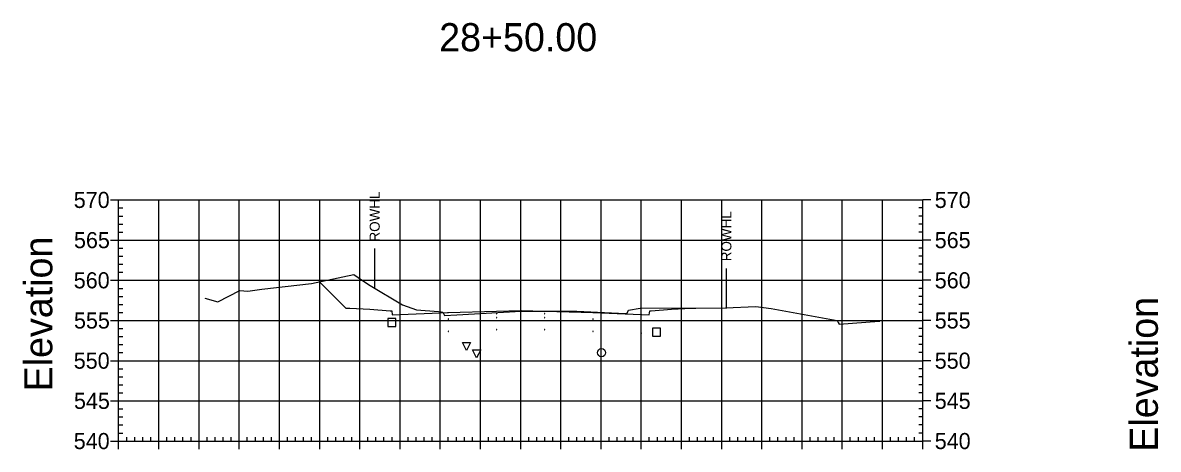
# Model space of a CAD drawing. Extents: x 708103 to 717568, y 374476 to 378707.
# Drawn here: x 710028.1 to 710310.6, y 377662.6 to 377768.7 of the extents above; entities that cross this region are included whole.
import ezdxf

# ---------------------------------------------------------------- set-up
doc = ezdxf.new("R2010")
doc.units = 0
for name, color, linetype in [('1', 7, 'Continuous'), ('10', 7, 'Continuous'), ('13', 7, 'Continuous'), ('14', 7, 'Continuous'), ('22', 7, 'Continuous'), ('4', 7, 'Continuous'), ('57', 7, 'Continuous'), ('60', 7, 'Continuous'), ('Existing', 7, 'Continuous'), ('XS_Right_of_Way', 7, 'Continuous')]:
    doc.layers.add(name, color=color, linetype=linetype)

msp = doc.modelspace()

# ---------------------------------------------------------------- linework, layer by layer
for points in [[(710145.93, 377696.27), (710146.03, 377696.27), (710146.03, 377696.37), (710145.93, 377696.37)], [(710151.93, 377696.39), (710152.03, 377696.39), (710152.03, 377696.49), (710151.93, 377696.49)], [(710157.93, 377696.27), (710158.03, 377696.27), (710158.03, 377696.37), (710157.93, 377696.37)], [(710121.93, 377694.43), (710122.03, 377694.43), (710122.03, 377694.53), (710121.93, 377694.53)], [(710133.93, 377694.91), (710134.03, 377694.91), (710134.03, 377695.01), (710133.93, 377695.01)], [(710145.93, 377695.27), (710146.03, 377695.27), (710146.03, 377695.37), (710145.93, 377695.37)], [(710151.93, 377695.39), (710152.03, 377695.39), (710152.03, 377695.49), (710151.93, 377695.49)], [(710157.93, 377695.27), (710158.03, 377695.27), (710158.03, 377695.37), (710157.93, 377695.37)], [(710169.93, 377694.91), (710170.03, 377694.91), (710170.03, 377695.01), (710169.93, 377695.01)], [(710181.93, 377694.43), (710182.03, 377694.43), (710182.03, 377694.53), (710181.93, 377694.53)], [(710121.93, 377691.43), (710122.03, 377691.43), (710122.03, 377691.53), (710121.93, 377691.53)], [(710133.93, 377691.91), (710134.03, 377691.91), (710134.03, 377692.01), (710133.93, 377692.01)], [(710145.93, 377692.27), (710146.03, 377692.27), (710146.03, 377692.37), (710145.93, 377692.37)], [(710151.93, 377692.39), (710152.03, 377692.39), (710152.03, 377692.49), (710151.93, 377692.49)], [(710157.93, 377692.27), (710158.03, 377692.27), (710158.03, 377692.37), (710157.93, 377692.37)], [(710169.93, 377691.91), (710170.03, 377691.91), (710170.03, 377692.01), (710169.93, 377692.01)], [(710181.93, 377691.43), (710182.03, 377691.43), (710182.03, 377691.53), (710181.93, 377691.53)]]:
    msp.add_lwpolyline(points, close=True)
at = {"layer": '1'}
for points in [[(710138.47, 377687.18), (710137.47, 377689.18), (710139.47, 377689.18)], [(710141.03, 377685.33), (710140.03, 377687.33), (710142.03, 377687.33)]]:
    msp.add_lwpolyline(points, close=True, dxfattribs=at)
at = {"layer": '10'}
msp.add_lwpolyline([(710118.92, 377693.1), (710120.92, 377693.1), (710120.92, 377695.1), (710118.92, 377695.1)], close=True, dxfattribs=at)
at = {"layer": '13'}
msp.add_circle((710172.09, 377686.62), 1, dxfattribs=at)
at = {"layer": '14'}
for points in [[(710101.93, 377704.26), (710101.93, 377704.31), (710101.93, 377704.26), (710101.88, 377704.26), (710101.93, 377704.26), (710101.93, 377704.21), (710101.93, 377704.26), (710101.98, 377704.26)], [(710121.98, 377696.15), (710121.98, 377696.2), (710121.98, 377696.15), (710121.93, 377696.15), (710121.98, 377696.15), (710121.98, 377696.1), (710121.98, 377696.15), (710122.03, 377696.15)], [(710133.98, 377696.63), (710133.98, 377696.68), (710133.98, 377696.63), (710133.93, 377696.63), (710133.98, 377696.63), (710133.98, 377696.58), (710133.98, 377696.63), (710134.03, 377696.63)], [(710151.98, 377697.11), (710151.98, 377697.16), (710151.98, 377697.11), (710151.93, 377697.11), (710151.98, 377697.11), (710151.98, 377697.06), (710151.98, 377697.11), (710152.03, 377697.11)], [(710169.98, 377696.63), (710169.98, 377696.68), (710169.98, 377696.63), (710169.93, 377696.63), (710169.98, 377696.63), (710169.98, 377696.58), (710169.98, 377696.63), (710170.03, 377696.63)], [(710181.98, 377696.15), (710181.98, 377696.2), (710181.98, 377696.15), (710181.93, 377696.15), (710181.98, 377696.15), (710181.98, 377696.1), (710181.98, 377696.15), (710182.03, 377696.15)], [(710195.5, 377697.72), (710195.5, 377697.77), (710195.5, 377697.72), (710195.45, 377697.72), (710195.5, 377697.72), (710195.5, 377697.67), (710195.5, 377697.72), (710195.55, 377697.72)]]:
    msp.add_lwpolyline(points, dxfattribs=at)
at = {"layer": '22'}
msp.add_lwpolyline([(710101.93, 377704.26), (710108.48, 377697.71), (710109.48, 377697.67), (710114.48, 377697.47), (710119.48, 377697.07), (710119.9, 377697.07), (710119.98, 377696.07), (710121.98, 377696.15), (710133.98, 377696.63), (710145.98, 377696.99), (710151.98, 377697.11), (710157.98, 377696.99), (710169.98, 377696.63), (710181.98, 377696.15), (710183.98, 377696.07), (710184.07, 377697.07), (710184.48, 377697.07), (710189.48, 377697.47), (710194.48, 377697.67), (710195.48, 377697.71), (710195.5, 377697.72)], dxfattribs=at)
at = {"layer": '4'}
msp.add_lwpolyline([(710184.8, 377690.69), (710186.8, 377690.69), (710186.8, 377692.69), (710184.8, 377692.69)], close=True, dxfattribs=at)
at = {"layer": '57'}
for p, q in [((710049.98, 377724.63), (710051.98, 377724.63)), ((710051.98, 377724.63), (710251.98, 377724.63)), ((710051.98, 377664.63), (710051.98, 377724.63)), ((710051.98, 377664.63), (710051.98, 377724.63)), ((710061.98, 377664.63), (710061.98, 377724.63)), ((710071.98, 377664.63), (710071.98, 377724.63)), ((710081.98, 377664.63), (710081.98, 377724.63)), ((710091.98, 377664.63), (710091.98, 377724.63)), ((710101.98, 377664.63), (710101.98, 377724.63)), ((710111.98, 377664.63), (710111.98, 377724.63)), ((710121.98, 377664.63), (710121.98, 377724.63)), ((710131.98, 377664.63), (710131.98, 377724.63)), ((710141.98, 377664.63), (710141.98, 377724.63)), ((710151.98, 377664.63), (710151.98, 377724.63)), ((710161.98, 377664.63), (710161.98, 377724.63)), ((710171.98, 377664.63), (710171.98, 377724.63)), ((710181.98, 377664.63), (710181.98, 377724.63)), ((710191.98, 377664.63), (710191.98, 377724.63)), ((710201.98, 377664.63), (710201.98, 377724.63)), ((710211.98, 377664.63), (710211.98, 377724.63)), ((710221.98, 377664.63), (710221.98, 377724.63)), ((710231.98, 377664.63), (710231.98, 377724.63)), ((710241.98, 377664.63), (710241.98, 377724.63)), ((710251.98, 377664.63), (710251.98, 377724.63)), ((710251.98, 377664.63), (710251.98, 377724.63)), ((710253.98, 377724.63), (710251.98, 377724.63)), ((710051.98, 377722.63), (710052.98, 377722.63)), ((710251.98, 377722.63), (710250.98, 377722.63)), ((710051.98, 377720.63), (710052.98, 377720.63)), ((710251.98, 377720.63), (710250.98, 377720.63)), ((710051.98, 377718.63), (710052.98, 377718.63)), ((710051.98, 377716.63), (710052.98, 377716.63)), ((710251.98, 377718.63), (710250.98, 377718.63)), ((710251.98, 377716.63), (710250.98, 377716.63)), ((710049.98, 377714.63), (710051.98, 377714.63)), ((710051.98, 377714.63), (710251.98, 377714.63)), ((710253.98, 377714.63), (710251.98, 377714.63)), ((710051.98, 377712.63), (710052.98, 377712.63)), ((710051.98, 377710.63), (710052.98, 377710.63)), ((710251.98, 377712.63), (710250.98, 377712.63)), ((710251.98, 377710.63), (710250.98, 377710.63)), ((710051.98, 377708.63), (710052.98, 377708.63)), ((710251.98, 377708.63), (710250.98, 377708.63)), ((710049.98, 377704.63), (710051.98, 377704.63)), ((710051.98, 377706.63), (710052.98, 377706.63)), ((710051.98, 377704.63), (710251.98, 377704.63)), ((710251.98, 377706.63), (710250.98, 377706.63)), ((710253.98, 377704.63), (710251.98, 377704.63)), ((710051.98, 377702.63), (710052.98, 377702.63)), ((710251.98, 377702.63), (710250.98, 377702.63)), ((710051.98, 377700.63), (710052.98, 377700.63)), ((710251.98, 377700.63), (710250.98, 377700.63)), ((710051.98, 377698.63), (710052.98, 377698.63)), ((710051.98, 377696.63), (710052.98, 377696.63)), ((710251.98, 377698.63), (710250.98, 377698.63)), ((710251.98, 377696.63), (710250.98, 377696.63)), ((710049.98, 377694.63), (710051.98, 377694.63)), ((710051.98, 377694.63), (710251.98, 377694.63)), ((710253.98, 377694.63), (710251.98, 377694.63)), ((710051.98, 377692.63), (710052.98, 377692.63)), ((710051.98, 377690.63), (710052.98, 377690.63)), ((710251.98, 377692.63), (710250.98, 377692.63)), ((710251.98, 377690.63), (710250.98, 377690.63)), ((710051.98, 377688.63), (710052.98, 377688.63)), ((710251.98, 377688.63), (710250.98, 377688.63)), ((710051.98, 377686.63), (710052.98, 377686.63)), ((710251.98, 377686.63), (710250.98, 377686.63)), ((710049.98, 377684.63), (710051.98, 377684.63)), ((710051.98, 377684.63), (710251.98, 377684.63)), ((710051.98, 377682.63), (710052.98, 377682.63)), ((710251.98, 377682.63), (710250.98, 377682.63)), ((710253.98, 377684.63), (710251.98, 377684.63)), ((710051.98, 377680.63), (710052.98, 377680.63)), ((710251.98, 377680.63), (710250.98, 377680.63)), ((710051.98, 377678.63), (710052.98, 377678.63)), ((710051.98, 377676.63), (710052.98, 377676.63)), ((710251.98, 377678.63), (710250.98, 377678.63)), ((710251.98, 377676.63), (710250.98, 377676.63)), ((710049.98, 377674.63), (710051.98, 377674.63)), ((710051.98, 377674.63), (710251.98, 377674.63)), ((710253.98, 377674.63), (710251.98, 377674.63)), ((710051.98, 377672.63), (710052.98, 377672.63)), ((710251.98, 377672.63), (710250.98, 377672.63)), ((710051.98, 377670.63), (710052.98, 377670.63)), ((710051.98, 377668.63), (710052.98, 377668.63)), ((710251.98, 377670.63), (710250.98, 377670.63)), ((710251.98, 377668.63), (710250.98, 377668.63)), ((710051.98, 377666.63), (710052.98, 377666.63)), ((710053.98, 377664.63), (710053.98, 377665.63)), ((710055.98, 377664.63), (710055.98, 377665.63)), ((710057.98, 377664.63), (710057.98, 377665.63)), ((710059.98, 377664.63), (710059.98, 377665.63)), ((710063.98, 377664.63), (710063.98, 377665.63)), ((710065.98, 377664.63), (710065.98, 377665.63)), ((710067.98, 377664.63), (710067.98, 377665.63)), ((710069.98, 377664.63), (710069.98, 377665.63)), ((710073.98, 377664.63), (710073.98, 377665.63)), ((710075.98, 377664.63), (710075.98, 377665.63)), ((710077.98, 377664.63), (710077.98, 377665.63)), ((710079.98, 377664.63), (710079.98, 377665.63)), ((710083.98, 377664.63), (710083.98, 377665.63)), ((710085.98, 377664.63), (710085.98, 377665.63)), ((710087.98, 377664.63), (710087.98, 377665.63)), ((710089.98, 377664.63), (710089.98, 377665.63)), ((710093.98, 377664.63), (710093.98, 377665.63)), ((710095.98, 377664.63), (710095.98, 377665.63)), ((710097.98, 377664.63), (710097.98, 377665.63)), ((710099.98, 377664.63), (710099.98, 377665.63)), ((710103.98, 377664.63), (710103.98, 377665.63)), ((710105.98, 377664.63), (710105.98, 377665.63)), ((710107.98, 377664.63), (710107.98, 377665.63)), ((710109.98, 377664.63), (710109.98, 377665.63)), ((710113.98, 377664.63), (710113.98, 377665.63)), ((710115.98, 377664.63), (710115.98, 377665.63)), ((710117.98, 377664.63), (710117.98, 377665.63)), ((710119.98, 377664.63), (710119.98, 377665.63)), ((710123.98, 377664.63), (710123.98, 377665.63)), ((710125.98, 377664.63), (710125.98, 377665.63)), ((710127.98, 377664.63), (710127.98, 377665.63)), ((710129.98, 377664.63), (710129.98, 377665.63)), ((710133.98, 377664.63), (710133.98, 377665.63)), ((710135.98, 377664.63), (710135.98, 377665.63)), ((710137.98, 377664.63), (710137.98, 377665.63)), ((710139.98, 377664.63), (710139.98, 377665.63)), ((710143.98, 377664.63), (710143.98, 377665.63)), ((710145.98, 377664.63), (710145.98, 377665.63)), ((710147.98, 377664.63), (710147.98, 377665.63)), ((710149.98, 377664.63), (710149.98, 377665.63)), ((710153.98, 377664.63), (710153.98, 377665.63)), ((710155.98, 377664.63), (710155.98, 377665.63)), ((710157.98, 377664.63), (710157.98, 377665.63)), ((710159.98, 377664.63), (710159.98, 377665.63)), ((710163.98, 377664.63), (710163.98, 377665.63)), ((710165.98, 377664.63), (710165.98, 377665.63)), ((710167.98, 377664.63), (710167.98, 377665.63)), ((710169.98, 377664.63), (710169.98, 377665.63)), ((710173.98, 377664.63), (710173.98, 377665.63)), ((710175.98, 377664.63), (710175.98, 377665.63)), ((710177.98, 377664.63), (710177.98, 377665.63)), ((710179.98, 377664.63), (710179.98, 377665.63)), ((710183.98, 377664.63), (710183.98, 377665.63)), ((710185.98, 377664.63), (710185.98, 377665.63)), ((710187.98, 377664.63), (710187.98, 377665.63)), ((710189.98, 377664.63), (710189.98, 377665.63)), ((710193.98, 377664.63), (710193.98, 377665.63)), ((710195.98, 377664.63), (710195.98, 377665.63)), ((710197.98, 377664.63), (710197.98, 377665.63)), ((710199.98, 377664.63), (710199.98, 377665.63)), ((710203.98, 377664.63), (710203.98, 377665.63)), ((710205.98, 377664.63), (710205.98, 377665.63)), ((710207.98, 377664.63), (710207.98, 377665.63)), ((710209.98, 377664.63), (710209.98, 377665.63)), ((710213.98, 377664.63), (710213.98, 377665.63)), ((710215.98, 377664.63), (710215.98, 377665.63)), ((710217.98, 377664.63), (710217.98, 377665.63)), ((710219.98, 377664.63), (710219.98, 377665.63)), ((710223.98, 377664.63), (710223.98, 377665.63)), ((710225.98, 377664.63), (710225.98, 377665.63)), ((710227.98, 377664.63), (710227.98, 377665.63)), ((710229.98, 377664.63), (710229.98, 377665.63)), ((710233.98, 377664.63), (710233.98, 377665.63)), ((710235.98, 377664.63), (710235.98, 377665.63)), ((710237.98, 377664.63), (710237.98, 377665.63)), ((710239.98, 377664.63), (710239.98, 377665.63)), ((710243.98, 377664.63), (710243.98, 377665.63)), ((710245.98, 377664.63), (710245.98, 377665.63)), ((710247.98, 377664.63), (710247.98, 377665.63)), ((710249.98, 377664.63), (710249.98, 377665.63)), ((710251.98, 377666.63), (710250.98, 377666.63)), ((710049.98, 377664.63), (710051.98, 377664.63)), ((710051.98, 377664.63), (710251.98, 377664.63)), ((710051.98, 377664.63), (710251.98, 377664.63)), ((710051.98, 377662.63), (710051.98, 377664.63)), ((710061.98, 377662.63), (710061.98, 377664.63)), ((710071.98, 377662.63), (710071.98, 377664.63)), ((710081.98, 377662.63), (710081.98, 377664.63)), ((710091.98, 377662.63), (710091.98, 377664.63)), ((710101.98, 377662.63), (710101.98, 377664.63)), ((710111.98, 377662.63), (710111.98, 377664.63)), ((710121.98, 377662.63), (710121.98, 377664.63)), ((710131.98, 377662.63), (710131.98, 377664.63)), ((710141.98, 377662.63), (710141.98, 377664.63)), ((710151.98, 377662.63), (710151.98, 377664.63)), ((710161.98, 377662.63), (710161.98, 377664.63)), ((710171.98, 377662.63), (710171.98, 377664.63)), ((710181.98, 377662.63), (710181.98, 377664.63)), ((710191.98, 377662.63), (710191.98, 377664.63)), ((710201.98, 377662.63), (710201.98, 377664.63)), ((710211.98, 377662.63), (710211.98, 377664.63)), ((710221.98, 377662.63), (710221.98, 377664.63)), ((710231.98, 377662.63), (710231.98, 377664.63)), ((710241.98, 377662.63), (710241.98, 377664.63)), ((710251.98, 377662.63), (710251.98, 377664.63)), ((710253.98, 377664.63), (710251.98, 377664.63))]:
    msp.add_line(p, q, dxfattribs=at)
at = {"layer": 'Existing'}
msp.add_lwpolyline([(710073.4, 377700.18), (710076.63, 377699.27), (710082.1, 377702.07), (710084.13, 377701.89), (710087.61, 377702.44), (710099.96, 377703.84), (710110.44, 377706.05), (710112.61, 377704.57), (710114.5, 377703.31), (710122.55, 377698.54), (710126.1, 377697.32), (710131.57, 377696.86), (710132.18, 377696.78), (710132.58, 377696.71), (710132.61, 377696.67), (710133.06, 377695.84), (710136.1, 377696.04), (710152.13, 377696.99), (710154.02, 377696.96), (710165.94, 377696.92), (710176.28, 377696.42), (710178.34, 377696.34), (710178.43, 377696.49), (710178.81, 377697.22), (710181.7, 377697.68), (710202.9, 377697.74), (710210.48, 377698.08), (710214.29, 377697.59), (710230.69, 377694.65), (710230.93, 377694.16), (710231.17, 377693.73), (710241.16, 377694.47), (710241.33, 377694.47), (710241.33, 377694.47)], dxfattribs=at)
at = {"layer": 'XS_Right_of_Way'}
for p, q in [((710115.6, 377712.52), (710115.6, 377702.52)), ((710203.08, 377707.61), (710203.08, 377697.61))]:
    msp.add_line(p, q, dxfattribs=at)

# ---------------------------------------------------------------- texts
at = {"layer": '1'}
msp.add_text('28+50.00', height=7, dxfattribs=at).set_placement((710131.71, 377761.63))
at = {"layer": '14'}
for p in [(710109.45, 377697.62), (710109.45, 377696.95), (710114.45, 377696.75), (710189.45, 377696.75), (710194.45, 377697.62), (710194.45, 377696.95)]:
    msp.add_text('+', height=0.1, dxfattribs=at).set_placement(p)
at = {"layer": '57'}
for s, p in [('570', (710040.81, 377722.63)), ('570', (710254.98, 377722.63)), ('565', (710040.86, 377712.63)), ('565', (710254.98, 377712.63)), ('560', (710040.81, 377702.63)), ('560', (710254.98, 377702.63)), ('555', (710040.86, 377692.63)), ('555', (710254.98, 377692.63)), ('550', (710040.81, 377682.63)), ('550', (710254.98, 377682.63)), ('545', (710040.86, 377672.63)), ('545', (710254.98, 377672.63)), ('540', (710040.81, 377662.63)), ('540', (710254.98, 377662.63))]:
    msp.add_text(s, height=4, dxfattribs=at).set_placement(p)
at = {"layer": '60'}
for p in [(710035.48, 377676.99), (710310.48, 377661.99)]:
    msp.add_text('Elevation', height=7, rotation=90, dxfattribs=at).set_placement(p)
at = {"layer": 'XS_Right_of_Way'}
for p in [(710116.92, 377714.28), (710204.4, 377709.37)]:
    msp.add_text('ROWHL', height=2.5, rotation=90, dxfattribs=at).set_placement(p)

doc.saveas('drawing.dxf')
